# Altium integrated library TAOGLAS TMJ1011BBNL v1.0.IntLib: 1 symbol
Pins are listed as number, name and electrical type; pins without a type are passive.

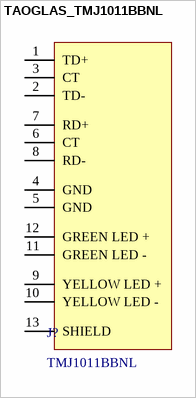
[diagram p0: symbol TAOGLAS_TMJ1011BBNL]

## TAOGLAS_TMJ1011BBNL
designator J?, comment TMJ1011BBNL
RJ45 connector with integrated magnetics 10/100Base-T Single Port Tab-UP with right angle THT mount and LEDs; ComponentLibStatus: Created; MFG: Taoglas; Temp_High: +85C; Temp_Low: -40C
footprint TAOGLAS_TMJ1011BBNL (RJ45 connector with integrated magnetics 10/100Base-T Single Port Tab-UP with right angle THT mount and LEDs)
pins: 1 TD+, 2 TD-, 3 CT, 4 GND, 5 GND, 6 CT, 7 RD+, 8 RD-, 9 YELLOW LED +, 10 YELLOW LED -, 11 GREEN LED -, 12 GREEN LED +, 13 SHIELD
